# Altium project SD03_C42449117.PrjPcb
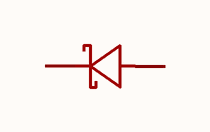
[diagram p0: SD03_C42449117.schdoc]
1 sheet, 1 parts. Net scope: global (net labels, ports and power ports of the same name join across sheets).

## Sheet SD03_C42449117.schdoc
size 127 x 101 mm

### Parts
D?  sd03_1  [SOD-323_L1.7-W1.3-LS2.5-RD]  (value not drawn)

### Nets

Not connected (* = marked no-connect by the designer): D? 1(K) 2(A)

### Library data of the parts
D? = sd03_1: 极性:单向;反向工作电压(Vrwm):3.3V;钳位电压:6.5V;峰值脉冲功率(Ppp):350W@8/20us;击穿电压(VBR):4V;; Manufacturer: JSMSEMI(杰盛微); ManufacturerPart: SD03; AddInBom: yes; SymbolName: SD03_C42449117; ModelId: 0f2f330c645944df9245ac3c3fec3456; ModelName: SOD-323_L1.7-W1.3-LS2.5-FD; ModelTransform: 98.425,49.2125,0,0,0,0,0,0,0; Polarity: 单向; Reverse Stand-Off Voltage (Vrwm): 3.3V; Clamping Voltage: 6.5V; Voltage - Breakdown: 4V; Reverse Leakage Current (Ir): 40uA; Number of Channels: 单路; level of protection: IEC 61000-4-4；IEC 61000-4-2; Junction Capacitance: 500pF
